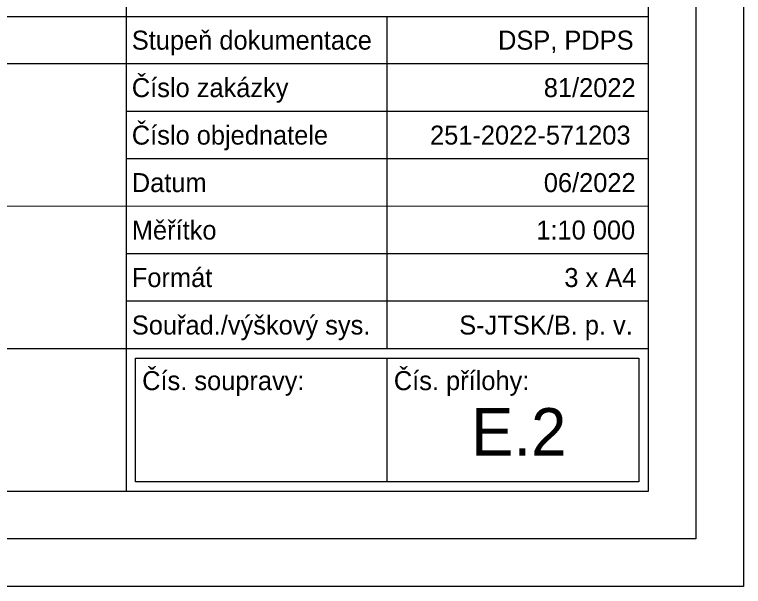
# Model space of a CAD drawing. Extents: x -521684 to -475491, y -1113264 to -1110290.
# Drawn here: x -476258 to -475491, y -1113261 to -1112658 of the extents above; entities that cross this region are included whole.
import ezdxf

# ---------------------------------------------------------------- set-up
doc = ezdxf.new("R2010")
doc.units = 0
doc.layers.add('rozpiska', color=7, linetype='Continuous')

msp = doc.modelspace()

# ---------------------------------------------------------------- linework, layer by layer
at = {"layer": 'rozpiska'}
for p, q in [((-476140.99, -1112360.26), (-476140.94, -1113160.26)), ((-475590.95, -1113160.23), (-475590.99, -1112360.23)), ((-475590.95, -1113160.23), (-475590.99, -1112363.04)), ((-477490.97, -1112660.33), (-475590.97, -1112660.23)), ((-475865.95, -1113010.24), (-475865.97, -1112660.24)), ((-475590.97, -1112710.23), (-477490.97, -1112710.33)), ((-475590.97, -1112760.23), (-476140.96, -1112760.26)), ((-475590.96, -1112810.23), (-476140.96, -1112810.26)), ((-475590.96, -1112860.23), (-477490.96, -1112860.33)), ((-475590.96, -1112910.23), (-476140.96, -1112910.26)), ((-475590.96, -1112960.23), (-476140.95, -1112960.26)), ((-475590.95, -1113010.23), (-477490.95, -1113010.33)), ((-475865.95, -1113150.24), (-475865.95, -1113020.24)), ((-477490.94, -1113160.33), (-475590.95, -1113160.23))]:
    msp.add_line(p, q, dxfattribs=at)
for points in [[(-475490.97, -1113260.53), (-481790.97, -1113260.53), (-481790.97, -1110290.43), (-475490.97, -1110290.43)], [(-475540.97, -1113210.48), (-481733.95, -1113210.48), (-481733.95, -1110340.43), (-475540.97, -1110340.43)], [(-476130.95, -1113020.26), (-475600.95, -1113020.23), (-475600.95, -1113150.23), (-476130.95, -1113150.26)]]:
    msp.add_lwpolyline(points, close=True, dxfattribs=at)

# ---------------------------------------------------------------- texts
for s, height, p in [('Stupeň dokumentace', 20, (-476134.97, -1112695.26)), ('DSP, PDPS', 20, (-475749.32, -1112695.25)), ('Číslo zakázky', 20, (-476134.96, -1112745.26)), ('81/2022', 20, (-475701.16, -1112745.25)), ('Číslo objednatele', 20, (-476134.96, -1112795.26)), ('251-2022-571203', 20, (-475820.94, -1112795.25)), ('Datum', 20, (-476134.96, -1112845.26)), ('06/2022', 20, (-475701.15, -1112845.25)), ('Měřítko', 20, (-476134.96, -1112895.26)), ('1:10 000', 20, (-475709.05, -1112895.25)), ('Formát', 20, (-476134.95, -1112945.26)), ('3 x A4', 20, (-475679.52, -1112945.25)), ('Souřad./výškový sys.', 20, (-476134.95, -1112995.26)), ('S-JTSK/B. p. v.', 20, (-475790.21, -1112995.25)), ('Čís. soupravy:', 20, (-476124.08, -1113053.84)), ('Čís. přílohy:', 20, (-475859.08, -1113053.83)), ('E.2', 50, (-475777.73, -1113122.77))]:
    msp.add_text(s, height=height, rotation=0.00292, dxfattribs=at).set_placement(p)

doc.saveas('drawing.dxf')
